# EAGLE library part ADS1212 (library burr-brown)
22-Bit Analog-to-Digital Converter
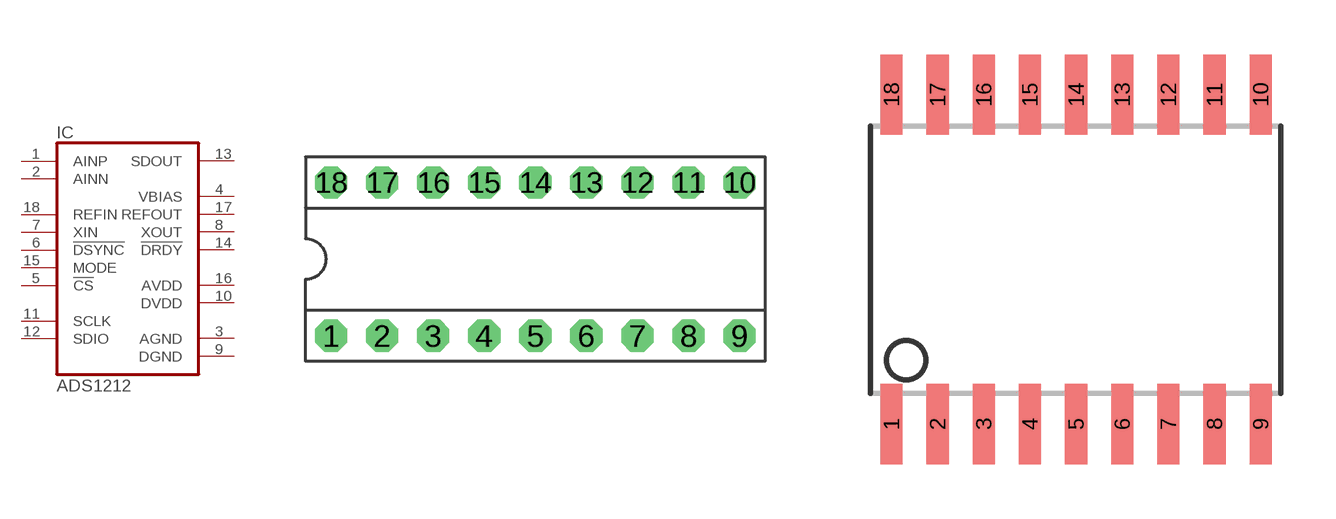
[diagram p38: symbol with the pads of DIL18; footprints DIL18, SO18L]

Designator prefix IC

## ADS1212P (MF: TEXAS INSTRUMENT CONNECTORS; MPN: ADS1212P; OC_FARNELL: unknown; OC_NEWARK: 96K4581)  [DIL18]
1  AINP  in
2  AINN  in
3  AGND  pwr
4  VBIAS  out
5  !CS  in
6  !DSYNC  in
7  XIN  in
8  XOUT  out
9  DGND  pwr
10  DVDD  pwr
11  SCLK
12  SDIO
13  SDOUT  out
14  !DRDY  out
15  MODE  in
16  AVDD  pwr
17  REFOUT  out
18  REFIN  in

## ADS1212U (MPN: ADS1212U; OC_FARNELL: 1459252; OC_NEWARK: 61M4770)  [SO18L]
Pads as for DIL18

## Footprint DIL18 (pad centres in mm)
Dual In Line
drill 0.813 pad 1.6 octagon: 1 -10.16,-3.81; 2 -7.62,-3.81; 3 -5.08,-3.81; 4 -2.54,-3.81; 5 0,-3.81; 6 2.54,-3.81; 7 5.08,-3.81; 8 7.62,-3.81; 9 10.16,-3.81; 10 10.16,3.81; 11 7.62,3.81; 12 5.08,3.81; 13 2.54,3.81; 14 0,3.81; 15 -2.54,3.81; 16 -5.08,3.81; 17 -7.62,3.81; 18 -10.16,3.81

## Footprint SO18L (pad centres in mm)
Small Outline Package, large
smd 0.61 x 2.21: 1 -5.08,-4.534; 2 -3.81,-4.534; 3 -2.54,-4.534; 4 -1.27,-4.534; 5 0,-4.534; 6 1.27,-4.534; 7 2.54,-4.534; 8 3.81,-4.534; 9 5.08,-4.534; 10 5.08,4.534; 11 3.81,4.534; 12 2.54,4.534; 13 1.27,4.534; 14 0,4.534; 15 -1.27,4.534; 16 -2.54,4.534; 17 -3.81,4.534; 18 -5.08,4.534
